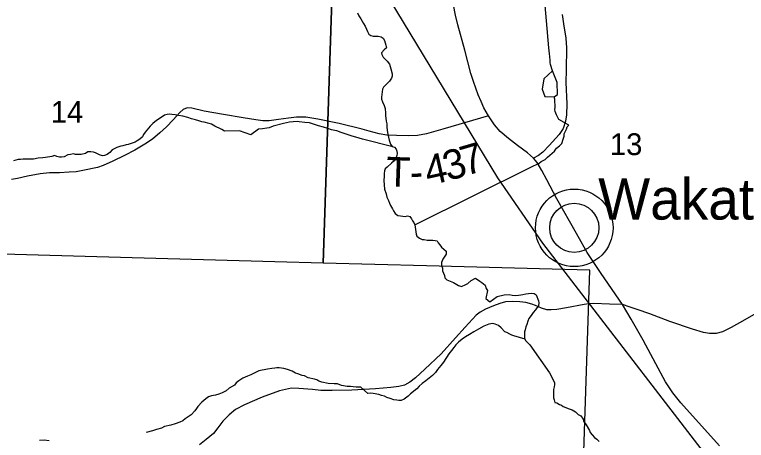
# Model space of a CAD drawing. Extents: x 0 to 34, y 0 to 22.
# Drawn here: x 3.454 to 4.859, y 18.529 to 19.347 of the extents above; entities that cross this region are included whole.
import ezdxf

# ---------------------------------------------------------------- set-up
doc = ezdxf.new("R2010")
doc.units = 0
for name, color, linetype in [('GM_X_Corporation', 7, 'Continuous'), ('GM_X_County_Road', 7, 'Continuous'), ('GM_X_Minor_Lake', 7, 'Continuous'), ('GM_X_Minor_River', 7, 'Continuous'), ('GM_X_Rail_Line', 7, 'Continuous'), ('GM_X_Section_Text', 7, 'Continuous'), ('GM_X_State_Route', 7, 'Continuous'), ('GM_X_Township_Road', 7, 'Continuous'), ('GM_X_Township_Road_Text', 7, 'Continuous'), ('GM_X_Unincorporated', 7, 'Continuous'), ('GM_X_Unincorporated_Location', 7, 'Continuous'), ('GM_X_Unincorporated_Text', 7, 'Continuous')]:
    doc.layers.add(name, color=color, linetype=linetype)

msp = doc.modelspace()

# ---------------------------------------------------------------- linework, layer by layer
at = {"layer": 'GM_X_Corporation'}
for points in [[(5.0447, 19.4257), (5.0167, 18.3983), (4.5438, 18.4054), (4.5458, 18.4688), (4.5582, 18.8561), (4.2447, 18.8641), (4.0466, 18.8695), (4.0627, 19.3751), (4.5724, 19.3635), (4.5747, 19.4359)], [(3.063, 19.4039), (4.0627, 19.3751), (4.0466, 18.8695), (3.9533, 18.8722), (3.6794, 18.8799), (3.3857, 18.8878), (3.0828, 18.8971), (3.0465, 18.8987)]]:
    msp.add_lwpolyline(points, close=True, dxfattribs=at)
at = {"layer": 'GM_X_County_Road'}
for points in [[(4.6208, 18.79), (4.5959, 18.791), (4.566, 18.7917), (4.5567, 18.7912), (4.5473, 18.79), (4.5135, 18.7835), (4.495, 18.7806), (4.4844, 18.7797), (4.4756, 18.7801), (4.4659, 18.7831), (4.4541, 18.7883), (4.4469, 18.791), (4.4356, 18.7937), (4.4239, 18.795), (4.4096, 18.7959), (4.3965, 18.795), (4.3857, 18.7923), (4.3735, 18.7878), (4.3579, 18.7808), (4.3475, 18.7754), (4.3401, 18.7695), (4.3193, 18.7467), (4.3006, 18.7259), (4.2728, 18.6955), (4.2414, 18.6659), (4.2238, 18.6494), (4.213, 18.641), (4.2028, 18.6354), (4.1917, 18.6325), (4.1764, 18.6307), (4.147, 18.6284), (4.1012, 18.6259), (4.0637, 18.6252), (4.0418, 18.6252), (4.0258, 18.6267), (3.9996, 18.6291), (3.9853, 18.6293), (3.9625, 18.6241), (3.9293, 18.6124), (3.8952, 18.5977), (3.8783, 18.5882), (3.8659, 18.5785), (3.8539, 18.5658), (3.8442, 18.5532), (3.8356, 18.5424), (3.822, 18.5311), (3.8087, 18.5207)], [(4.9258, 18.792), (4.9133, 18.7892), (4.8967, 18.7826), (4.8818, 18.7751), (4.856, 18.7606), (4.8297, 18.7459), (4.8129, 18.7375), (4.8008, 18.7345), (4.7883, 18.7345), (4.7769, 18.7364), (4.7556, 18.7429), (4.712, 18.7577), (4.6735, 18.7721), (4.6495, 18.7802), (4.6359, 18.7847), (4.6208, 18.79)], [(3.5203, 18.5281), (3.5108, 18.5295), (3.5018, 18.5288)]]:
    msp.add_lwpolyline(points, dxfattribs=at)
at = {"layer": 'GM_X_Minor_Lake'}
for points in [[(4.487, 19.239), (4.47, 19.2234), (4.4666, 19.2033), (4.4723, 19.1896), (4.4898, 19.1885)], [(4.4898, 19.1885), (4.4966, 19.1935), (4.4958, 19.2162), (4.487, 19.239)]]:
    msp.add_lwpolyline(points, dxfattribs=at)
at = {"layer": 'GM_X_Minor_River'}
for points in [[(4.487, 19.239), (4.4831, 19.2511), (4.4824, 19.2549), (4.482, 19.2587), (4.4816, 19.2663), (4.4812, 19.2712), (4.4796, 19.2826), (4.471, 19.3869)], [(4.1123, 19.3498), (4.1146, 19.3441), (4.1188, 19.3388), (4.121, 19.3343), (4.1241, 19.3293), (4.1268, 19.3244), (4.1298, 19.3187), (4.1313, 19.3142), (4.134, 19.3092), (4.1378, 19.3066), (4.1423, 19.3051), (4.1465, 19.3051), (4.1518, 19.3055), (4.1575, 19.304), (4.1617, 19.3017), (4.164, 19.2968), (4.167, 19.2877), (4.1678, 19.2831), (4.1636, 19.2793), (4.1584, 19.2736), (4.1591, 19.2698), (4.1614, 19.2649), (4.1656, 19.2611), (4.1694, 19.257), (4.1736, 19.2517), (4.1763, 19.2426), (4.1786, 19.2327), (4.1786, 19.2285), (4.1774, 19.2244), (4.1737, 19.2187), (4.168, 19.2133), (4.162, 19.2076), (4.1605, 19.2035), (4.1597, 19.1985), (4.159, 19.1936), (4.1582, 19.1883), (4.1586, 19.1841), (4.1602, 19.1792), (4.1636, 19.1724), (4.1651, 19.1663), (4.1659, 19.1572), (4.1659, 19.1523), (4.1667, 19.1481), (4.1675, 19.1424), (4.1686, 19.1367), (4.1686, 19.131), (4.1694, 19.1242), (4.1706, 19.1174), (4.1721, 19.1113), (4.1733, 19.1056), (4.1759, 19.098), (4.1786, 19.0935), (4.1835, 19.092), (4.1866, 19.0882), (4.1877, 19.0844), (4.1885, 19.0802)], [(4.2221, 18.9433), (4.4462, 19.0542), (4.4504, 19.0565), (4.4561, 19.0587), (4.4602, 19.061), (4.4651, 19.0644), (4.4727, 19.0686), (4.4769, 19.0728), (4.4814, 19.077), (4.4908, 19.0842), (4.4946, 19.0903), (4.4999, 19.0945), (4.5048, 19.099), (4.5071, 19.1074), (4.5089, 19.1131), (4.5093, 19.1176), (4.5112, 19.1218), (4.5135, 19.1267), (4.515, 19.1309), (4.518, 19.1347), (4.499, 19.1453), (4.4967, 19.1491), (4.4944, 19.1544), (4.4921, 19.1605), (4.4914, 19.1642), (4.4917, 19.1688), (4.4917, 19.1734), (4.4913, 19.1787), (4.4909, 19.1844), (4.4898, 19.1885)], [(4.1803, 19.093), (4.1217, 19.1078), (4.1153, 19.1097), (4.1092, 19.1116), (4.102, 19.1131), (4.0883, 19.1176), (4.0808, 19.1206), (4.0728, 19.1233), (4.069, 19.1244), (4.0626, 19.1255), (4.055, 19.1278), (4.047, 19.1304), (4.0375, 19.1334), (4.0337, 19.1346), (4.028, 19.1365), (4.0201, 19.1387), (4.0114, 19.1398), (4.0004, 19.141), (3.9962, 19.1413), (3.9886, 19.1409), (3.9814, 19.1402), (3.9757, 19.139), (3.9701, 19.1375), (3.9504, 19.1325), (3.9424, 19.1295), (3.9379, 19.1287), (3.9296, 19.1272), (3.9224, 19.1268), (3.9076, 19.1161), (3.886, 19.1233), (3.8568, 19.1229), (3.8519, 19.1259), (3.8466, 19.1285), (3.8424, 19.1308), (3.8382, 19.1327), (3.8318, 19.1365), (3.8272, 19.1376), (3.8177, 19.1402), (3.8132, 19.141), (3.8075, 19.1425), (3.8011, 19.1444), (3.7938, 19.1466), (3.7866, 19.1493), (3.7768, 19.1519), (3.7684, 19.153), (3.762, 19.1545), (3.7559, 19.1549), (3.7506, 19.1553), (3.7468, 19.1549), (3.7419, 19.1538), (3.737, 19.1503), (3.7264, 19.1435), (3.7196, 19.1378), (3.7139, 19.1325), (3.7049, 19.1211), (3.7015, 19.1165), (3.6992, 19.1119), (3.6943, 19.1074), (3.6894, 19.1043), (3.6852, 19.1017), (3.6799, 19.0998), (3.672, 19.0971), (3.6682, 19.0967), (3.6618, 19.0948), (3.6576, 19.094), (3.65, 19.0917), (3.6413, 19.0868), (3.6368, 19.0822), (3.6315, 19.0781), (3.6266, 19.0761), (3.6228, 19.0758), (3.6171, 19.0773), (3.6133, 19.0795), (3.6091, 19.0814), (3.6053, 19.0826), (3.6, 19.0833), (3.5944, 19.0829), (3.5898, 19.0802), (3.5819, 19.0783), (3.5709, 19.0783), (3.5667, 19.0791), (3.561, 19.0783), (3.5561, 19.0772), (3.5489, 19.0737), (3.544, 19.073), (3.5398, 19.0729), (3.5349, 19.0741), (3.5307, 19.076), (3.5254, 19.0744), (3.5133, 19.0725), (3.508, 19.0717), (3.4989, 19.071), (3.4902, 19.0694), (3.4803, 19.0694), (3.4697, 19.069), (3.4652, 19.0686), (3.4606, 19.0686), (3.4519, 19.066)], [(4.1885, 19.0802), (4.1881, 19.0764), (4.1859, 19.0711), (4.1828, 19.0662), (4.1776, 19.0613), (4.1692, 19.054), (4.1651, 19.0506), (4.164, 19.0464), (4.1636, 19.0415), (4.1632, 19.0366), (4.1629, 19.0282), (4.1633, 19.0199), (4.1644, 19.0115), (4.1675, 19.0024), (4.1687, 18.9964), (4.1721, 18.9899), (4.1736, 18.9846), (4.1755, 18.9801), (4.1793, 18.974), (4.1812, 18.9699), (4.1843, 18.9649), (4.1896, 18.9611), (4.1949, 18.96), (4.1995, 18.9596), (4.204, 18.9593), (4.2086, 18.96), (4.2127, 18.9593), (4.2158, 18.9547), (4.2177, 18.951), (4.2203, 18.9472), (4.2222, 18.943), (4.2234, 18.9339), (4.225, 18.9252), (4.2261, 18.9214), (4.2314, 18.9176), (4.2367, 18.915), (4.2405, 18.9146), (4.2458, 18.9135), (4.2496, 18.9135), (4.2568, 18.9135), (4.2614, 18.9131), (4.2655, 18.9124), (4.2674, 18.9082), (4.2705, 18.9044), (4.2735, 18.8999), (4.2826, 18.8923), (4.2823, 18.887), (4.2759, 18.8771), (4.2736, 18.871), (4.2736, 18.865), (4.2752, 18.8597), (4.2756, 18.8547), (4.2794, 18.8456), (4.2798, 18.8415), (4.2839, 18.8373), (4.2904, 18.835), (4.2965, 18.832), (4.306, 18.8267), (4.312, 18.8248), (4.32, 18.8286), (4.3241, 18.8306), (4.3306, 18.8359), (4.3389, 18.8404), (4.3472, 18.8351), (4.351, 18.8325), (4.3571, 18.8272), (4.3594, 18.8211), (4.3617, 18.817), (4.3587, 18.8018), (4.3663, 18.7954), (4.3807, 18.8052), (4.3939, 18.8087), (4.4034, 18.8095), (4.4091, 18.808), (4.4163, 18.8076), (4.4216, 18.808), (4.4258, 18.8084), (4.4299, 18.8091), (4.4356, 18.8107), (4.4409, 18.8114), (4.4473, 18.8118), (4.4515, 18.8115), (4.4553, 18.8088), (4.4599, 18.7974), (4.4607, 18.7933), (4.4595, 18.7876), (4.4565, 18.7834), (4.4539, 18.7796), (4.4497, 18.7747), (4.4471, 18.7709), (4.4441, 18.7667), (4.441, 18.7629), (4.4392, 18.7583), (4.4373, 18.7515), (4.4354, 18.7473), (4.4339, 18.7416), (4.4332, 18.7378), (4.4332, 18.725), (4.4355, 18.7204), (4.4431, 18.7125), (4.4811, 18.6591)], [(4.4339, 18.7236), (4.4123, 18.7302), (4.4086, 18.731), (4.4048, 18.7329), (4.3991, 18.7366), (4.3953, 18.7378), (4.3884, 18.7453), (4.3827, 18.7495), (4.3767, 18.7525), (4.3721, 18.7537), (4.3642, 18.7521), (4.3551, 18.7487), (4.3449, 18.743), (4.3354, 18.7377), (4.3275, 18.7327), (4.3199, 18.7281), (4.3131, 18.7232), (4.3063, 18.7175), (4.3014, 18.7126), (4.2972, 18.7076), (4.2927, 18.7019), (4.2878, 18.6955), (4.2772, 18.6795), (4.2723, 18.6727), (4.2659, 18.6651), (4.2618, 18.6594), (4.2561, 18.6537), (4.25, 18.6484), (4.2436, 18.6434), (4.2364, 18.6381), (4.2308, 18.6335), (4.2259, 18.6282), (4.2138, 18.6183), (4.2096, 18.6142), (4.2017, 18.6085), (4.1964, 18.6058), (4.1918, 18.6058), (4.1876, 18.6065), (4.1823, 18.6073), (4.1748, 18.6099), (4.1687, 18.6118), (4.1641, 18.6141), (4.1584, 18.6152), (4.1531, 18.6171), (4.1421, 18.6193), (4.1368, 18.6197), (4.1323, 18.6193), (4.119, 18.6314), (4.1099, 18.6314), (4.1038, 18.6322), (4.0989, 18.6325), (4.0925, 18.6329), (4.0818, 18.6348), (4.0739, 18.6378), (4.0678, 18.6378), (4.0557, 18.6385), (4.0436, 18.6408), (4.0382, 18.643), (4.0341, 18.6457), (4.0299, 18.6464), (4.0178, 18.6494), (4.0102, 18.6528), (4.006, 18.654), (3.9977, 18.657), (3.9935, 18.6581), (3.987, 18.6619), (3.9776, 18.6653), (3.9711, 18.6672), (3.9666, 18.6679), (3.962, 18.6683), (3.9571, 18.6683), (3.9533, 18.6679), (3.9476, 18.6675), (3.9393, 18.666), (3.923, 18.6625), (3.9075, 18.6553), (3.9011, 18.6522), (3.892, 18.6488), (3.8844, 18.6435), (3.8795, 18.6397), (3.8761, 18.6355), (3.8659, 18.6294), (3.8598, 18.6245), (3.8523, 18.6203), (3.8462, 18.6176), (3.8398, 18.6161), (3.8322, 18.6146), (3.8261, 18.6127), (3.8212, 18.6092), (3.8133, 18.6028), (3.8054, 18.5944), (3.8031, 18.5902), (3.7997, 18.5857), (3.7929, 18.5781), (3.7812, 18.5705), (3.7767, 18.5667), (3.771, 18.5644), (3.7623, 18.561), (3.7536, 18.5583), (3.7418, 18.556), (3.7358, 18.5529)], [(4.4811, 18.6591), (4.4872, 18.6466), (4.4907, 18.6397), (4.4907, 18.6359), (4.4896, 18.6321), (4.4884, 18.6268), (4.4885, 18.6174), (4.4889, 18.6109), (4.49, 18.6071), (4.4912, 18.6018), (4.4953, 18.6011), (4.4999, 18.598), (4.5037, 18.5969), (4.5075, 18.5943), (4.512, 18.592), (4.5166, 18.5905), (4.5246, 18.5875), (4.5306, 18.5841), (4.536, 18.5791), (4.5413, 18.5761), (4.5455, 18.5697), (4.5462, 18.5659), (4.5516, 18.5591), (4.558, 18.5481), (4.5592, 18.5443), (4.563, 18.5398), (4.5672, 18.5345), (4.5721, 18.5318), (4.5763, 18.5269)], [(3.7358, 18.5529), (3.7263, 18.5503), (3.7187, 18.5476), (3.7062, 18.5442)]]:
    msp.add_lwpolyline(points, dxfattribs=at)
at = {"layer": 'GM_X_Rail_Line'}
msp.add_lwpolyline([(4.8515, 18.4096), (4.468, 18.9077), (4.382, 19.0334), (4.1748, 19.3749), (3.8527, 19.8843), (3.6877, 20.1234), (3.6615, 20.1661), (3.5505, 20.339), (3.4927, 20.4317), (3.4483, 20.5097), (3.4202, 20.6049), (3.4057, 20.6941), (3.4068, 20.7593), (3.4191, 20.8537), (3.4357, 20.9)], dxfattribs=at)
at = {"layer": 'GM_X_State_Route'}
for points in [[(4.3635, 19.1521), (4.3551, 19.168), (4.3497, 19.1798), (4.3442, 19.1925), (4.3352, 19.2182), (4.3301, 19.2339), (4.3183, 19.2784), (4.3051, 19.3272), (4.3002, 19.3455), (4.2967, 19.3652)], [(4.4504, 19.0712), (4.4389, 19.0813), (4.4195, 19.0952), (4.4023, 19.1091), (4.3865, 19.1225), (4.3752, 19.1351), (4.3635, 19.1521)], [(4.8073, 18.5186), (4.7328, 18.6012), (4.7177, 18.6205), (4.7038, 18.6416), (4.6849, 18.6763), (4.6608, 18.7213), (4.6378, 18.762), (4.6208, 18.79), (4.5801, 18.8496), (4.5533, 18.89), (4.5418, 18.9104), (4.5325, 18.9262), (4.4951, 18.993), (4.4758, 19.0294), (4.4664, 19.0471), (4.4571, 19.0629), (4.4504, 19.0712)]]:
    msp.add_lwpolyline(points, dxfattribs=at)
at = {"layer": 'GM_X_Township_Road'}
for points in [[(4.5052, 19.3467), (4.5078, 19.329), (4.5126, 19.3013), (4.5136, 19.2828), (4.5131, 19.2405), (4.5121, 19.2165), (4.514, 19.1754), (4.5136, 19.1541), (4.5114, 19.1421), (4.5073, 19.1282), (4.4997, 19.1162), (4.4805, 19.0954), (4.4679, 19.0827), (4.4597, 19.0763), (4.4504, 19.0712)], [(4.3635, 19.1521), (4.3484, 19.1476), (4.2762, 19.1264), (4.2446, 19.1175), (4.2272, 19.1147), (4.2102, 19.1138), (4.1872, 19.1147), (4.1689, 19.1153), (4.1537, 19.118), (4.1346, 19.1229), (4.1213, 19.1266), (4.0774, 19.1375), (4.0359, 19.1461), (4.0129, 19.1496), (3.9953, 19.1498), (3.9799, 19.1481), (3.9606, 19.145), (3.9425, 19.1428), (3.9302, 19.1428), (3.9168, 19.1444), (3.893, 19.1485), (3.8549, 19.1549), (3.8179, 19.1615), (3.7941, 19.1668), (3.7853, 19.1674), (3.7775, 19.1643), (3.7709, 19.1586), (3.7582, 19.1444), (3.7455, 19.1311), (3.7329, 19.1198), (3.7186, 19.1077), (3.7042, 19.098), (3.6845, 19.0863), (3.6648, 19.0759), (3.6428, 19.0654), (3.6242, 19.057), (3.6131, 19.0533), (3.585, 19.0473), (3.572, 19.0447), (3.5585, 19.0439), (3.54, 19.0426), (3.5209, 19.0426), (3.5031, 19.041), (3.4788, 19.0363), (3.4593, 19.032), (3.448, 19.0301)], [(4.4504, 19.0712), (4.4389, 19.0813), (4.4195, 19.0952), (4.4023, 19.1091), (4.3865, 19.1225), (4.3752, 19.1351), (4.3635, 19.1521)]]:
    msp.add_lwpolyline(points, dxfattribs=at)
at = {"layer": 'GM_X_Unincorporated'}
for radius in [0.0744, 0.0472]:
    msp.add_circle((4.5285, 18.9373), radius, dxfattribs=at)
at = {"layer": 'GM_X_Unincorporated_Location'}
msp.add_line((4.5285, 18.9373), (4.5285, 18.9373), dxfattribs=at)

# ---------------------------------------------------------------- texts
at = {"layer": 'GM_X_Section_Text'}
for s, p in [('14', (3.5233, 19.1389)), ('13', (4.597, 19.0769))]:
    msp.add_text(s, height=0.04186, rotation=0, dxfattribs=at).set_placement(p)
at = {"layer": 'GM_X_Township_Road_Text'}
for s, rotation, p in [('7', 16.3826, (4.3195, 19.0366)), ('4', 12.4855, (4.2477, 19.0183)), ('3', 16.1405, (4.2857, 19.0268)), ('T', 357.9554, (4.1663, 19.0171)), ('-', 2.9706, (4.2142, 19.0157))]:
    msp.add_text(s, height=0.0568, rotation=rotation, dxfattribs=at).set_placement(p)
at = {"layer": 'GM_X_Unincorporated_Text'}
msp.add_text('Wakatomika', height=0.07898, rotation=0, dxfattribs=at).set_placement((4.5745, 18.9531))

doc.saveas('drawing.dxf')
